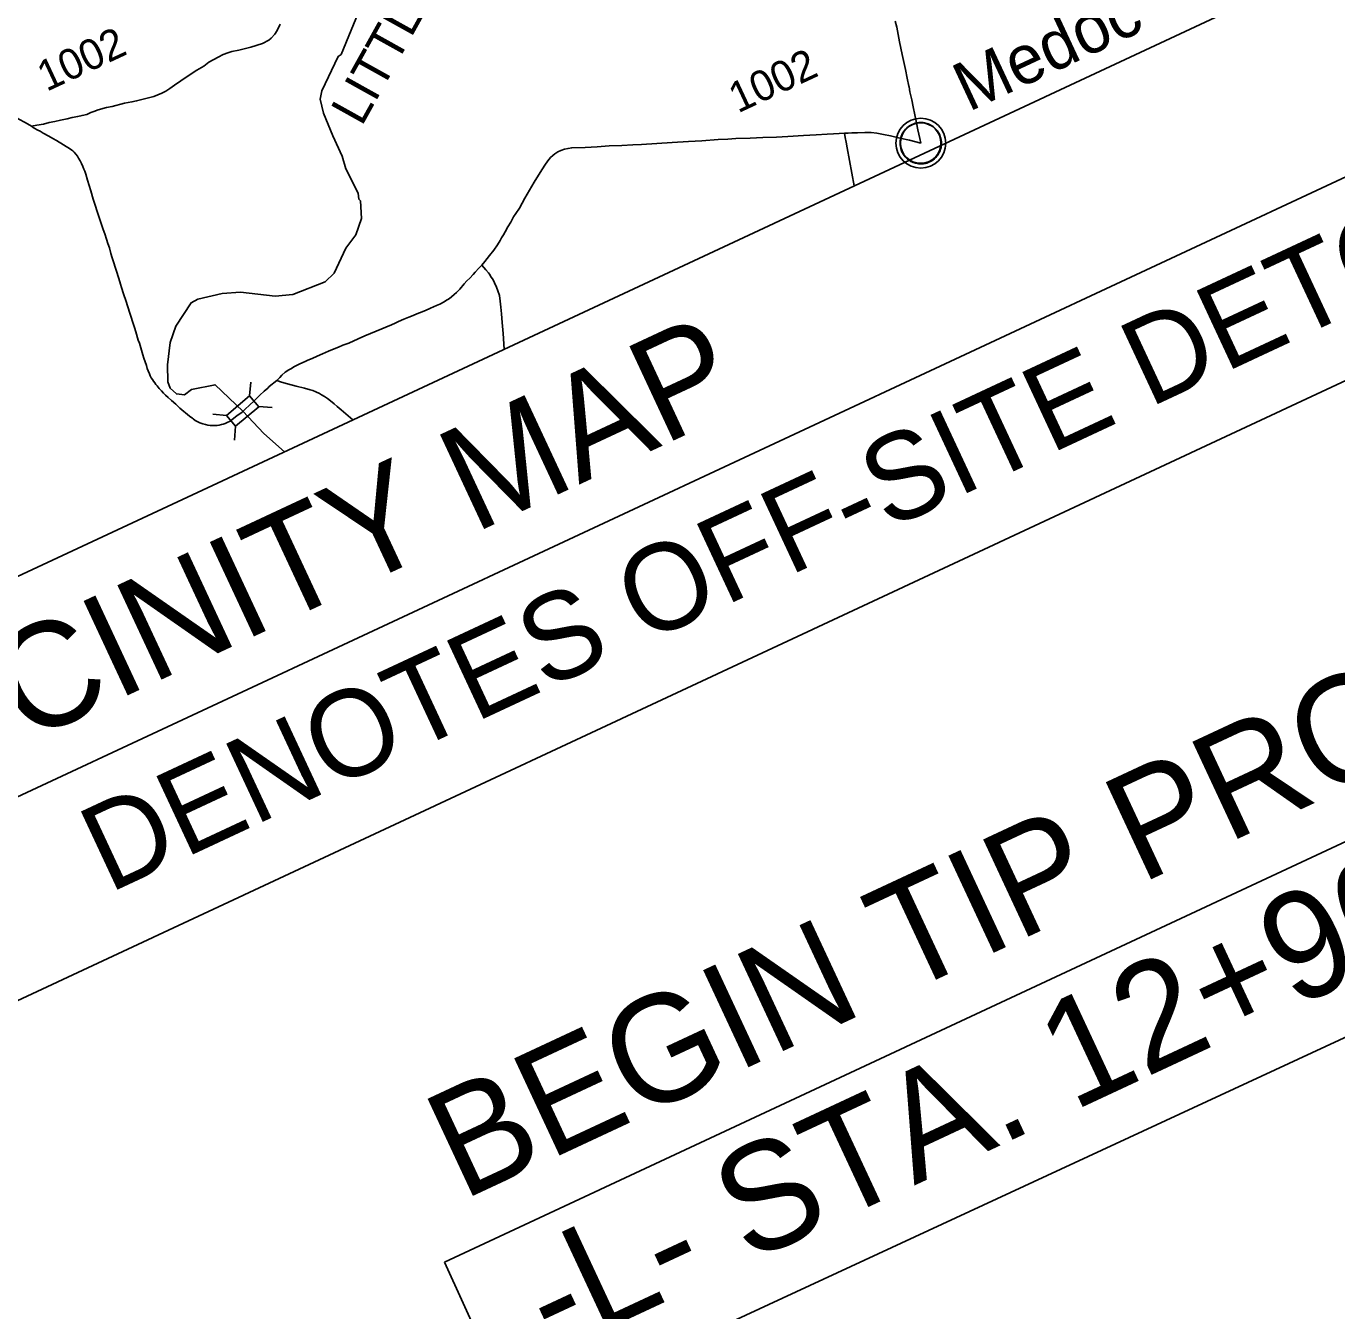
# Model space of a CAD drawing. Extents: x 2318983 to 2324558, y 920396 to 924651.
# Drawn here: x 2320702 to 2321231, y 922262 to 922780 of the extents above; entities that cross this region are included whole.
import ezdxf

# ---------------------------------------------------------------- set-up
doc = ezdxf.new("R2010")
doc.units = 0
for name, color, linetype in [('Default', 7, 'Continuous'), ('Exist Civil Demographics City Label', 7, 'Continuous'), ('Exist Civil Demographics Community CELL', 7, 'Continuous'), ('Exist Hydrographic Creek Single Shore', 7, 'Continuous'), ('Exist Road Primary NC Attributed', 7, 'Continuous'), ('Exist Road Secondary Structure Standard Bridge CELL', 7, 'Continuous'), ('Exist Road Secondary Type 51 Attributed', 7, 'Continuous'), ('Exist Road Secondary Type 51 Number Label', 7, 'Continuous'), ('Pattern 3', 7, 'Continuous'), ('Prop Dimension', 7, 'Continuous'), ('Prop DSN Text', 7, 'Continuous')]:
    doc.layers.add(name, color=color, linetype=linetype)

msp = doc.modelspace()

# ---------------------------------------------------------------- linework, layer by layer
at = {"layer": 'Exist Civil Demographics Community CELL'}
msp.add_lwpolyline([(2321054.84, 922733.76), (2321054.95, 922734.36), (2321055.14, 922735.06), (2321055.45, 922735.82), (2321055.76, 922736.43), (2321056.11, 922737.04), (2321056.51, 922737.59), (2321056.93, 922738.05), (2321057.42, 922738.54), (2321058.01, 922739.03), (2321058.59, 922739.42), (2321059.1, 922739.72), (2321059.64, 922739.98), (2321060.22, 922740.23), (2321060.82, 922740.42), (2321061.28, 922740.54), (2321061.8, 922740.62), (2321062.23, 922740.7), (2321062.91, 922740.72), (2321063.38, 922740.71), (2321063.98, 922740.69), (2321064.51, 922740.61), (2321065.03, 922740.5), (2321065.56, 922740.35), (2321066.11, 922740.15), (2321066.82, 922739.84), (2321067.48, 922739.47), (2321068.02, 922739.09), (2321068.57, 922738.66), (2321068.92, 922738.33), (2321069.36, 922737.86), (2321069.77, 922737.36), (2321070.1, 922736.88), (2321070.43, 922736.34), (2321070.69, 922735.79), (2321070.91, 922735.26), (2321071.07, 922734.73), (2321071.21, 922734.24), (2321071.32, 922733.6), (2321071.39, 922733.1), (2321071.42, 922732.46), (2321071.4, 922731.85), (2321071.34, 922731.24), (2321071.24, 922730.66), (2321071.06, 922730), (2321070.86, 922729.38), (2321070.62, 922728.85), (2321070.28, 922728.21), (2321069.94, 922727.64), (2321069.57, 922727.14), (2321069.12, 922726.64), (2321068.56, 922726.11), (2321068.02, 922725.67), (2321067.49, 922725.31), (2321067.03, 922725.04), (2321066.31, 922724.7), (2321065.55, 922724.41), (2321064.92, 922724.25), (2321064.21, 922724.11), (2321063.74, 922724.06), (2321063.27, 922724.04), (2321062.67, 922724.04), (2321062.22, 922724.08), (2321061.62, 922724.16), (2321060.99, 922724.3), (2321060.5, 922724.44), (2321059.95, 922724.64), (2321059.46, 922724.85), (2321059.05, 922725.09), (2321058.33, 922725.52), (2321057.73, 922725.97), (2321057.21, 922726.45), (2321056.74, 922726.97), (2321056.4, 922727.39), (2321056.08, 922727.83), (2321055.65, 922728.58), (2321055.46, 922728.96), (2321055.28, 922729.39), (2321055.01, 922730.26), (2321054.84, 922731.01), (2321054.77, 922731.56), (2321054.73, 922732.23), (2321054.73, 922732.73), (2321054.79, 922733.42)], close=True, dxfattribs=at)
for centre, radius in [((2321063.09, 922732.44), 10.03), ((2321063.06, 922732.47), 8.15)]:
    msp.add_circle(centre, radius, dxfattribs=at)
at = {"layer": 'Exist Hydrographic Creek Single Shore'}
for points in [[(2320820.96, 922750.14), (2320821.58, 922753.55), (2320828.2, 922767.39), (2320829.43, 922768.16), (2320838.41, 922790.01), (2320851.15, 922805.96), (2320852.36, 922809.81), (2320852.28, 922814.97), (2320850.02, 922817.62), (2320847.34, 922818.97), (2320838.11, 922819.31)], [(2320806.59, 922608.05), (2320798.21, 922615.39), (2320789.76, 922624.44), (2320778.58, 922635.03), (2320769.12, 922633.08), (2320766.3, 922631.03), (2320763, 922631.38), (2320760.51, 922633.62), (2320759.48, 922636.24), (2320759.4, 922643.02), (2320760.53, 922652.03), (2320762.7, 922658.66), (2320768.97, 922668.13), (2320771.61, 922669.61), (2320781.43, 922671.79), (2320788.81, 922672.41), (2320802.76, 922670.72), (2320809.91, 922671.42), (2320822.98, 922676.48), (2320826.65, 922680.02), (2320831.25, 922690.15), (2320835.28, 922695.48), (2320837.67, 922702.04), (2320837.18, 922709.21), (2320836.56, 922709.83), (2320836.32, 922712.32), (2320831.3, 922722.13), (2320829.82, 922727.23), (2320826.03, 922735.4), (2320822.24, 922744.53), (2320820.96, 922750.14)]]:
    msp.add_lwpolyline(points, dxfattribs=at)
at = {"layer": 'Exist Road Primary NC Attributed'}
msp.add_lwpolyline([(2321063.09, 922732.44), (2321062.67, 922734.33), (2321061.94, 922737.75), (2321061.4, 922740.59), (2321060.71, 922743.82), (2321060.06, 922747.09), (2321059.41, 922749.95), (2321058.72, 922753.05), (2321058.37, 922755.06), (2321058.29, 922755.4), (2321057.58, 922758.58), (2321056.93, 922762.12), (2321055.57, 922768.17), (2321054.43, 922773.33), (2321053.38, 922779.17), (2321052.78, 922781.53)], dxfattribs=at)
at = {"layer": 'Exist Road Secondary Structure Standard Bridge CELL'}
for p, q in [((2320792.5, 922630.54), (2320792.96, 922636.09)), ((2320777.62, 922623.15), (2320783.17, 922622.68)), ((2320796.09, 922626.29), (2320801.64, 922625.83)), ((2320786.38, 922612.78), (2320786.85, 922618.33))]:
    msp.add_line(p, q, dxfattribs=at)
msp.add_lwpolyline([(2320783.17, 922622.68), (2320792.48, 922630.56), (2320796.16, 922626.21), (2320786.85, 922618.33)], close=True, dxfattribs=at)
at = {"layer": 'Exist Road Secondary Type 51 Attributed'}
for points in [[(2320804.83, 922780.32), (2320803.63, 922777.88), (2320802.68, 922776.4), (2320801.18, 922774.75), (2320800.23, 922773.95), (2320797.74, 922772.55), (2320792.94, 922771.05), (2320788.1, 922769.96), (2320785.4, 922769.36), (2320783.7, 922768.78), (2320781.81, 922768.13), (2320779.81, 922767.13), (2320776.11, 922765.03), (2320774.05, 922763.43), (2320771.21, 922761.78), (2320768.16, 922759.78), (2320764.72, 922757.58), (2320762.27, 922755.83), (2320760.32, 922754.48), (2320758.68, 922753.38), (2320757.18, 922752.63), (2320755.53, 922751.93), (2320753.88, 922751.29), (2320746.94, 922749.44), (2320745.04, 922749.04), (2320742.05, 922748.54), (2320737.1, 922747.24), (2320734.81, 922746.74), (2320731.51, 922745.84), (2320729.66, 922745.19), (2320728.56, 922744.74), (2320726.92, 922744), (2320724.96, 922743.59), (2320723.24, 922743.23), (2320721.03, 922742.76), (2320718.92, 922742.24), (2320716.32, 922741.67), (2320713.97, 922741.11), (2320711.71, 922740.69), (2320709.35, 922740.13), (2320706.75, 922739.66), (2320704.64, 922739.24)], [(2320649.52, 922767.2), (2320657.3, 922764.7), (2320659.35, 922763.77), (2320660.2, 922763.4), (2320663.14, 922762.04), (2320671.6, 922757.31), (2320682.09, 922751.67), (2320687.38, 922748.62), (2320688.64, 922748.02), (2320690.3, 922747.13), (2320698.36, 922742.71), (2320699.45, 922742.03), (2320702.02, 922740.69), (2320704.64, 922739.24)], [(2320704.64, 922739.24), (2320705.64, 922738.41), (2320707.12, 922737.64), (2320708.01, 922737.21), (2320709.29, 922736.48), (2320711.52, 922735.28), (2320713.2, 922734.31), (2320714.64, 922733.44), (2320720.28, 922729.96), (2320720.83, 922729.57), (2320721.27, 922729.28), (2320721.77, 922728.85), (2320722.47, 922728.02), (2320723.07, 922727.14), (2320723.57, 922726.31), (2320724.17, 922725.28), (2320724.77, 922724.2), (2320725.28, 922723.08), (2320725.73, 922722), (2320726.04, 922721.07), (2320726.44, 922719.89), (2320727.11, 922717.54), (2320728.48, 922713.22), (2320729.5, 922709.79), (2320729.86, 922708.61), (2320731.49, 922703.67), (2320733.47, 922697.64), (2320734.08, 922695.92), (2320734.79, 922693.67), (2320735.35, 922692), (2320735.96, 922690.29), (2320736.62, 922687.98), (2320737.13, 922686.26), (2320738.92, 922680.43), (2320740.14, 922676.55), (2320740.4, 922675.53), (2320740.9, 922674.2), (2320741.72, 922671.65), (2320742.74, 922668.62), (2320743.25, 922666.85), (2320745.54, 922659.69), (2320746.14, 922658.08), (2320746.6, 922656.31), (2320747.63, 922653.03), (2320748.08, 922651.8), (2320749.51, 922647.09), (2320749.92, 922645.77), (2320750.89, 922642.83), (2320751.24, 922641.61), (2320751.6, 922640.68), (2320752.1, 922639.45), (2320752.45, 922638.67), (2320752.86, 922637.83), (2320753.31, 922637.2), (2320753.8, 922636.47), (2320754.25, 922635.83), (2320754.75, 922635.2), (2320755.3, 922634.56), (2320756.05, 922633.59), (2320756.95, 922632.56), (2320757.79, 922631.64), (2320758.54, 922630.91), (2320759.63, 922629.89), (2320761.07, 922628.67), (2320762.81, 922627.17), (2320764.4, 922625.61), (2320768.25, 922622.43), (2320768.75, 922622.02), (2320769.47, 922621.55), (2320769.76, 922621.3), (2320770.57, 922620.7), (2320771.36, 922620.26), (2320772.37, 922619.73), (2320773.59, 922619.35), (2320774.22, 922619.13), (2320774.69, 922619), (2320775.67, 922618.78), (2320776.64, 922618.59), (2320778.34, 922618.59), (2320779.44, 922618.69), (2320780.29, 922618.78), (2320781.17, 922618.97), (2320781.87, 922619.1), (2320782.65, 922619.47), (2320783.44, 922619.85), (2320784.6, 922620.42), (2320785.45, 922621.05), (2320787.37, 922622.46)], [(2320886.07, 922683.3), (2320887.3, 922684.71), (2320889.15, 922687.1), (2320890.94, 922689.31), (2320892.39, 922691.43), (2320893.49, 922693.2), (2320894.1, 922694.21), (2320894.81, 922695.47), (2320895.48, 922696.71), (2320896.6, 922698.71), (2320897.78, 922700.64), (2320898.93, 922702.72), (2320899.81, 922704.04), (2320901.26, 922706.27), (2320903.4, 922710.31), (2320907.16, 922716.69), (2320909.67, 922720.56), (2320911.55, 922723.53), (2320912.66, 922725.27), (2320913.83, 922726.61), (2320914.8, 922727.46), (2320915.58, 922728.16), (2320916.75, 922728.91), (2320917.98, 922729.42), (2320919.5, 922729.97), (2320920.92, 922730.28), (2320922.34, 922730.55), (2320927.75, 922730.71), (2320932.57, 922730.97), (2320937.39, 922731.32), (2320942.59, 922731.53), (2320946.97, 922731.73), (2320950.46, 922731.92), (2320956.71, 922732.29), (2320962.9, 922732.66), (2320969.44, 922733.03), (2320974.85, 922733.35), (2320981.35, 922733.85), (2320985.25, 922734.07), (2320988.47, 922734.25), (2320994.35, 922734.42), (2320999.42, 922734.71), (2321004.9, 922734.88), (2321009.48, 922735.14), (2321015.76, 922735.49), (2321020.91, 922735.76), (2321025.27, 922736.06), (2321027.86, 922736.24), (2321030.17, 922736.33), (2321032.32, 922736.41)], [(2321032.32, 922736.41), (2321033.74, 922736.49), (2321035.32, 922736.52), (2321036.58, 922736.56), (2321037.58, 922736.56), (2321040.54, 922736.71), (2321043.11, 922736.67), (2321045.3, 922736.4), (2321048.07, 922735.89), (2321050.82, 922735.43), (2321054.66, 922734.41), (2321058.52, 922733.61), (2321063.09, 922732.44)], [(2321032.32, 922736.41), (2321032.55, 922734.72), (2321032.93, 922732.83), (2321033.33, 922730.58), (2321036.23, 922715.23)], [(2320803.41, 922636.75), (2320804.64, 922637.95), (2320805.55, 922638.95), (2320806.84, 922640.09), (2320808.25, 922641.03), (2320809.36, 922641.66), (2320810.33, 922642.23), (2320811.62, 922642.92), (2320812.72, 922643.42), (2320814.86, 922644.37), (2320815.96, 922644.96), (2320817.66, 922645.69), (2320819.77, 922646.6), (2320821.84, 922647.51), (2320824.33, 922648.62), (2320826.56, 922649.53), (2320828.35, 922650.25), (2320830.02, 922650.94), (2320832.54, 922651.86), (2320836.28, 922653.62), (2320838.95, 922654.82), (2320843.48, 922656.67), (2320849.68, 922659.25), (2320851.16, 922659.91), (2320852.51, 922660.51), (2320854.74, 922661.49), (2320856.69, 922662.34), (2320858.42, 922663), (2320859.96, 922663.6), (2320861, 922664.04), (2320863.45, 922665.04), (2320865.47, 922665.92), (2320867.83, 922666.96), (2320869.12, 922667.56), (2320870.87, 922668.52), (2320871.46, 922668.86), (2320873.07, 922669.87), (2320873.85, 922670.42), (2320875, 922671.43), (2320875.85, 922672.22), (2320877.2, 922673.51), (2320878.99, 922675.68), (2320880.12, 922676.88), (2320881.29, 922678.04), (2320882.61, 922679.42), (2320883.49, 922680.49), (2320884.91, 922682.01), (2320886.07, 922683.3)], [(2320886.07, 922683.3), (2320887.77, 922681.34), (2320888.74, 922680.12), (2320889.18, 922679.68), (2320889.5, 922679.2), (2320889.65, 922678.83), (2320890.63, 922677.32), (2320891.29, 922676.15), (2320892.01, 922674.36), (2320892.58, 922672.94), (2320893.18, 922670.96), (2320893.56, 922668.76), (2320893.78, 922666.3), (2320894.03, 922663.63), (2320894.34, 922660.17), (2320894.72, 922655.66), (2320895.18, 922649.4)], [(2320787.37, 922622.46), (2320789.48, 922624.04), (2320790.61, 922625.01), (2320792.62, 922626.9), (2320794.23, 922628.41), (2320796.65, 922630.87), (2320798.38, 922632.47), (2320799.83, 922633.7), (2320800.45, 922634.3), (2320803.41, 922636.75)], [(2320803.41, 922636.75), (2320805.39, 922636.12), (2320807.78, 922635.4), (2320811.33, 922634.5), (2320814.64, 922633.67), (2320816.96, 922632.99), (2320818, 922632.67), (2320819.16, 922632.23), (2320820.67, 922631.48), (2320821.46, 922631.04), (2320822.65, 922630.25), (2320823.85, 922629.46), (2320825.07, 922628.55), (2320826.58, 922627.39), (2320827.75, 922626.25), (2320829.35, 922624.99), (2320834.1, 922620.9)]]:
    msp.add_lwpolyline(points, dxfattribs=at)
at = {"layer": 'Pattern 3'}
msp.add_line((2320435.73, 922346.11), (2321310.81, 922754.51), dxfattribs=at)
msp.add_lwpolyline([(2320401.68, 922419.08), (2321276.76, 922827.48), (2321342.28, 922687.08), (2320467.2, 922278.68)], close=True, dxfattribs=at)
at = {"layer": 'Prop Dimension'}
msp.add_line((2320815.91, 922178.3), (2322085.86, 922766.57), dxfattribs=at)
at = {"layer": 'Prop DSN Text'}
for q in [(2321601.55, 922622.35), (2321042.59, 921904.95)]:
    msp.add_line((2320871.09, 922281.43), q, dxfattribs=at)

# ---------------------------------------------------------------- texts
at = {"layer": 'Default'}
msp.add_text('LITTLE', height=14.881, rotation=60.8997, dxfattribs=at).set_placement((2320837.69, 922738.86))
at = {"layer": 'Exist Civil Demographics City Label'}
msp.add_text('Medoc', height=19.683, rotation=25.0187, dxfattribs=at).set_placement((2321082.35, 922744.9))
at = {"layer": 'Exist Road Secondary Type 51 Number Label'}
for p in [(2320710.63, 922753.05), (2320989.36, 922744.36)]:
    msp.add_text('1002', height=12.302, rotation=25.0187, dxfattribs=at).set_placement(p)
at = {"layer": 'Pattern 3'}
for s, height, p in [('DENOTES OFF-SITE DETOUR', 34.8, (2320735.77, 922429.9)), ('VICINITY MAP', 42, (2320653.81, 922468.05))]:
    msp.add_text(s, height=height, rotation=25.0187, dxfattribs=at).set_placement(p)
at = {"layer": 'Prop DSN Text'}
for s, p in [('BEGIN TIP PROJECT B-4761', (2320878.23, 922306.1)), ('-L- STA. 12+90.00', (2320914.95, 922244.35))]:
    msp.add_text(s, height=43.2, rotation=25.0187, dxfattribs=at).set_placement(p)

doc.saveas('drawing.dxf')
